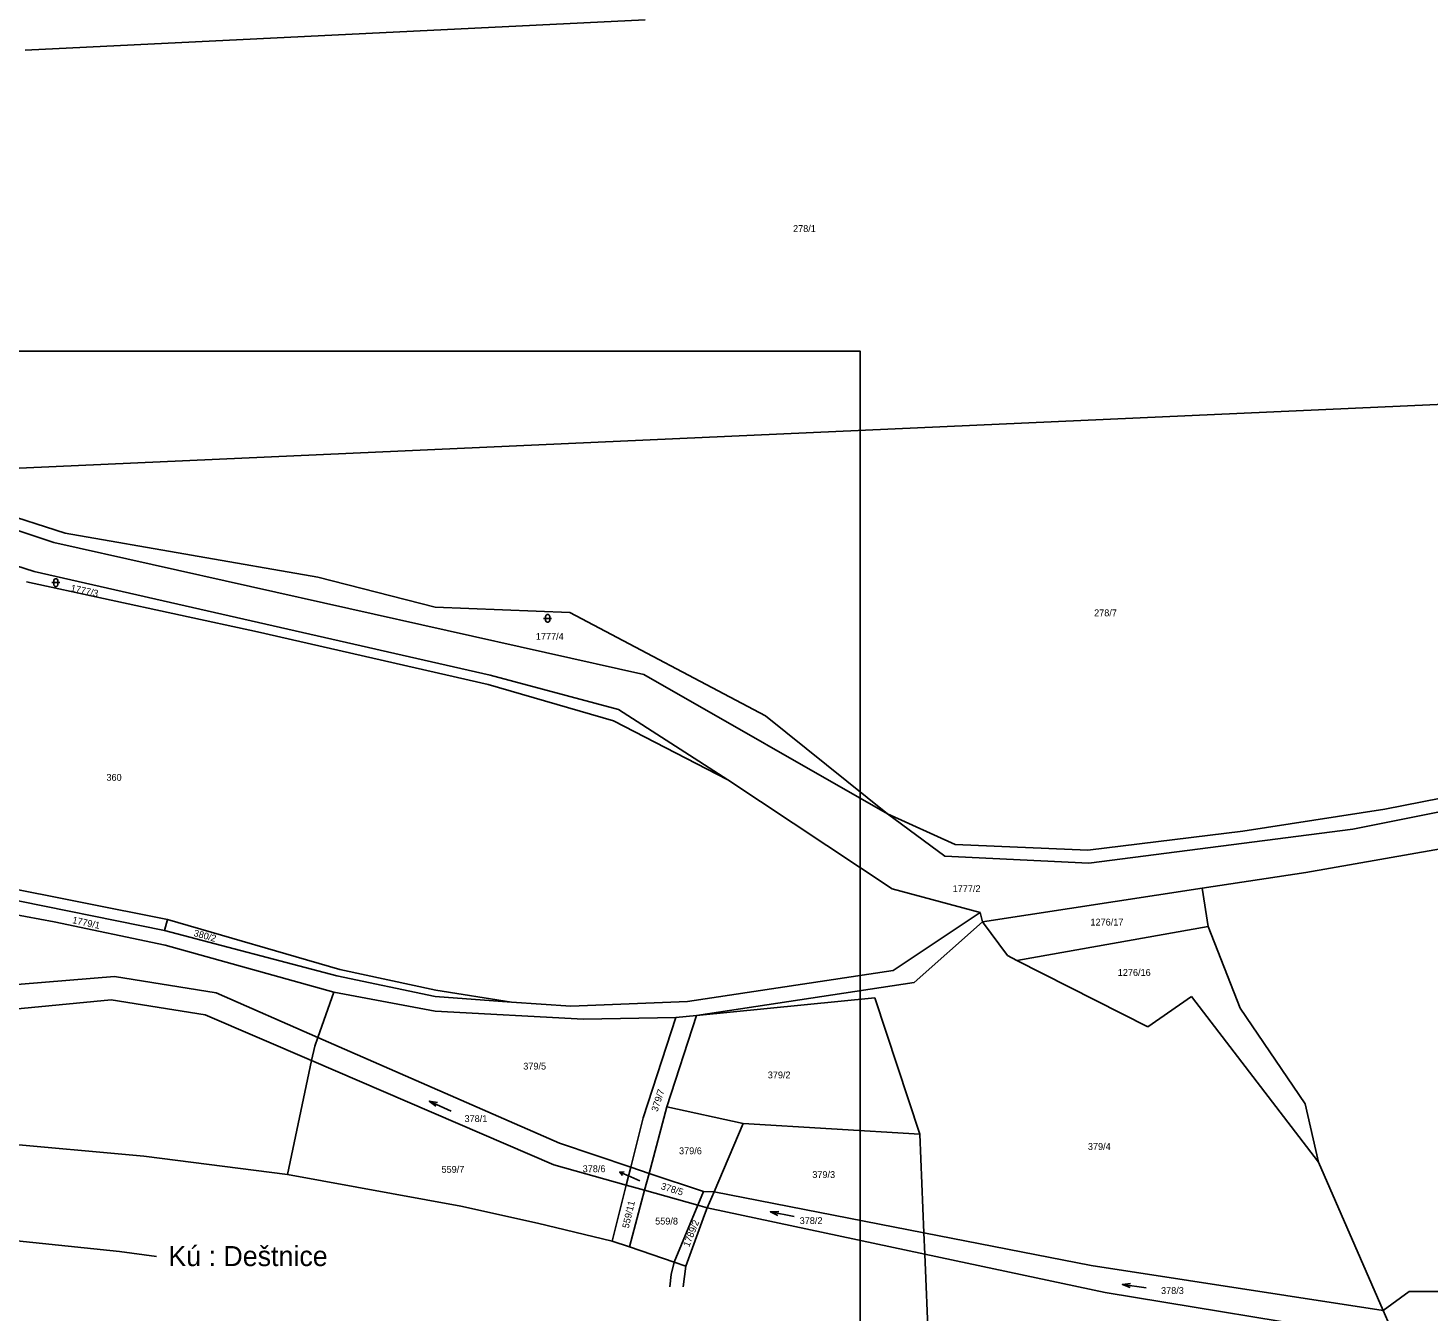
# Model space of a CAD drawing. Extents: x -799786 to -795190, y -1021716 to -1017834.
# Drawn here: x -798627.9 to -798278.5, y -1019029 to -1018708.6 of the extents above; entities that cross this region are included whole.
import ezdxf

# ---------------------------------------------------------------- set-up
doc = ezdxf.new("R2010")
doc.units = 0
for name, color, linetype in [('Default', 7, 'Continuous'), ('KN_HRANICE', 7, 'Continuous'), ('KN_KULTURY', 7, 'Continuous'), ('KN_PARCELY', 7, 'Continuous'), ('KN_SLUCKY', 7, 'Continuous'), ('LEGENDA', 7, 'Continuous')]:
    doc.layers.add(name, color=color, linetype=linetype)

# ---------------------------------------------------------------- blocks, each defined once
blk = doc.blocks.new('316')
at = {"layer": 'Default'}
for points in [[(-1, 1), (0.27, 1), (1, 1)], [(-0.5, 1.5), (-0.4, 1.79), (-0.15, 1.97), (0.16, 1.97), (0.41, 1.79), (0.51, 1.5), (0.51, 0.5), (0.41, 0.21), (0.16, 0.03), (-0.15, 0.03), (-0.4, 0.21), (-0.5, 0.5), (-0.5, 1.5)]]:
    blk.add_lwpolyline(points, dxfattribs=at)
blk = doc.blocks.new('802')
at = {"layer": 'Default'}
blk.add_line((-3, 0), (3, 0), dxfattribs=at)
blk.add_lwpolyline([(1, 0.5), (3, 0), (1, -0.5)], dxfattribs=at)
blk = doc.blocks.new('10292')
at = {"layer": 'Default'}
blk.add_line((0, 3), (0, 0), dxfattribs=at)
blk.add_lwpolyline([(-0.5, 2), (0, 3), (0.5, 2)], dxfattribs=at)

msp = doc.modelspace()

# ---------------------------------------------------------------- linework, layer by layer
at = {"layer": 'KN_HRANICE'}
for p, q in [((-798628.58, -1018714.18), (-798473.83, -1018706.61)), ((-798648.58, -1018819.28), (-798164.43, -1018797.57)), ((-798670.97, -1018817.82), (-798618.58, -1018834.64)), ((-798670.05, -1018820.82), (-798621.41, -1018836.96)), ((-798626.28, -1018844.22), (-798653.49, -1018835.57)), ((-798618.58, -1018834.64), (-798555.54, -1018845.61)), ((-798621.41, -1018836.96), (-798474.17, -1018869.95)), ((-798626.28, -1018844.22), (-798512.51, -1018870.06)), ((-798555.54, -1018845.61), (-798526.25, -1018853.09)), ((-798628.2, -1018846.85), (-798570.58, -1018859.25)), ((-798526.25, -1018853.09), (-798492.65, -1018854.49)), ((-798492.65, -1018854.49), (-798443.82, -1018880.26)), ((-798570.58, -1018859.25), (-798513.02, -1018872.39)), ((-798512.51, -1018870.06), (-798480.48, -1018878.64)), ((-798474.17, -1018869.95), (-798413.42, -1018904.71)), ((-798513.02, -1018872.39), (-798481.79, -1018881.47)), ((-798289.26, -1018903.57), (-798140.92, -1018874.27)), ((-798481.79, -1018881.47), (-798453.21, -1018896.22)), ((-798480.48, -1018878.64), (-798453.21, -1018896.22)), ((-798443.82, -1018880.26), (-798413.42, -1018904.71)), ((-798297.3, -1018908.51), (-798181.63, -1018885.44)), ((-798453.21, -1018896.22), (-798412.19, -1018923.42)), ((-798413.42, -1018904.71), (-798399.11, -1018915.28)), ((-798413.42, -1018904.71), (-798396.51, -1018912.35)), ((-798324.7, -1018909.02), (-798289.26, -1018903.57)), ((-798309.02, -1018919.33), (-798225.73, -1018904.69)), ((-798363.41, -1018913.79), (-798324.7, -1018909.02)), ((-798363.16, -1018917), (-798297.3, -1018908.51)), ((-798396.51, -1018912.35), (-798363.41, -1018913.79)), ((-798399.11, -1018915.28), (-798363.16, -1018917)), ((-798334.83, -1018923.26), (-798309.02, -1018919.33)), ((-798646.5, -1018923.14), (-798593.8, -1018933.78)), ((-798644.85, -1018920.76), (-798593.08, -1018931.09)), ((-798412.19, -1018923.42), (-798390.27, -1018929.32)), ((-798389.65, -1018931.6), (-798334.83, -1018923.26)), ((-798333.38, -1018932.83), (-798334.83, -1018923.26)), ((-798646.74, -1018926.95), (-798621.31, -1018931.61)), ((-798411.98, -1018943.8), (-798390.27, -1018929.32)), ((-798390.27, -1018929.32), (-798389.65, -1018931.6)), ((-798621.31, -1018931.61), (-798593.59, -1018937.5)), ((-798593.08, -1018931.09), (-798593.8, -1018933.78)), ((-798593.8, -1018933.78), (-798550.83, -1018945.14)), ((-798593.08, -1018931.09), (-798550.03, -1018943.53)), ((-798406.71, -1018946.8), (-798389.65, -1018931.6)), ((-798383.44, -1018940.08), (-798389.65, -1018931.6)), ((-798333.38, -1018932.83), (-798381.11, -1018941.26)), ((-798593.59, -1018937.5), (-798551.56, -1018949.18)), ((-798381.11, -1018941.26), (-798383.44, -1018940.08)), ((-798550.03, -1018943.53), (-798526.1, -1018948.66)), ((-798463.3, -1018951.51), (-798411.98, -1018943.8)), ((-798348.39, -1018957.83), (-798381.11, -1018941.26)), ((-798653.61, -1018949.12), (-798606.28, -1018945.31)), ((-798606.28, -1018945.31), (-798580.93, -1018949.34)), ((-798550.83, -1018945.14), (-798526.25, -1018950.31)), ((-798461.06, -1018954.98), (-798406.71, -1018946.8)), ((-798639.41, -1018954.22), (-798607.1, -1018951.14)), ((-798607.1, -1018951.14), (-798583.64, -1018954.81)), ((-798580.93, -1018949.34), (-798555.55, -1018960.46)), ((-798551.56, -1018949.18), (-798555.55, -1018960.46)), ((-798551.56, -1018949.18), (-798526.25, -1018953.93)), ((-798526.25, -1018950.31), (-798507.23, -1018951.65)), ((-798526.1, -1018948.66), (-798507.23, -1018951.65)), ((-798461.06, -1018954.98), (-798416.56, -1018950.62)), ((-798405.32, -1018984.59), (-798416.56, -1018950.62)), ((-798337.55, -1018950.26), (-798348.39, -1018957.83)), ((-798305.84, -1018991.62), (-798337.55, -1018950.26)), ((-798583.64, -1018954.81), (-798557.08, -1018966.24)), ((-798526.25, -1018953.93), (-798489.23, -1018955.9)), ((-798507.23, -1018951.65), (-798492.44, -1018952.69)), ((-798492.44, -1018952.69), (-798463.3, -1018951.51)), ((-798489.23, -1018955.9), (-798466.19, -1018955.48)), ((-798466.19, -1018955.48), (-798474.39, -1018980.52)), ((-798468.45, -1018977.76), (-798461.06, -1018954.98)), ((-798466.19, -1018955.48), (-798461.06, -1018954.98)), ((-798555.55, -1018960.46), (-798556.31, -1018962.63)), ((-798555.55, -1018960.46), (-798495.22, -1018986.9)), ((-798556.31, -1018962.63), (-798557.08, -1018966.24)), ((-798557.08, -1018966.24), (-798563.11, -1018994.64)), ((-798557.08, -1018966.24), (-798496.64, -1018992.23)), ((-798468.45, -1018977.76), (-798472.87, -1018994.39)), ((-798449.39, -1018981.94), (-798468.45, -1018977.76)), ((-798474.39, -1018980.52), (-798477.47, -1018992.85)), ((-798449.39, -1018981.94), (-798456.64, -1018999)), ((-798449.39, -1018981.94), (-798405.32, -1018984.59)), ((-798659.98, -1018984.53), (-798598.93, -1018990.13)), ((-798404.31, -1019009.25), (-798405.32, -1018984.59)), ((-798495.22, -1018986.9), (-798477.47, -1018992.85)), ((-798598.93, -1018990.13), (-798563.11, -1018994.64)), ((-798496.64, -1018992.23), (-798478.58, -1018997.32)), ((-798477.47, -1018992.85), (-798478.58, -1018997.32)), ((-798477.47, -1018992.85), (-798472.87, -1018994.39)), ((-798305.84, -1018991.62), (-798289.67, -1019028.59)), ((-798563.11, -1018994.64), (-798519.87, -1019002.61)), ((-798472.87, -1018994.39), (-798473.99, -1018998.61)), ((-798472.87, -1018994.39), (-798459.27, -1018998.94)), ((-798478.58, -1018997.32), (-798482.07, -1019011.28)), ((-798478.58, -1018997.32), (-798473.99, -1018998.61)), ((-798473.99, -1018998.61), (-798477.75, -1019012.75)), ((-798473.99, -1018998.61), (-798460.7, -1019002.36)), ((-798459.27, -1018998.94), (-798460.7, -1019002.36)), ((-798459.27, -1018998.94), (-798456.64, -1018999)), ((-798456.64, -1018999), (-798404.31, -1019009.25)), ((-798519.87, -1019002.61), (-798500.68, -1019006.85)), ((-798460.7, -1019002.36), (-798466.63, -1019016.52)), ((-798460.7, -1019002.36), (-798458.35, -1019003.02)), ((-798458.35, -1019003.02), (-798459.09, -1019004.76)), ((-798458.35, -1019003.02), (-798404.09, -1019014.54)), ((-798500.68, -1019006.85), (-798482.07, -1019011.28)), ((-798463.72, -1019017.51), (-798459.09, -1019004.76)), ((-798404.31, -1019009.25), (-798362.55, -1019017.42)), ((-798404.09, -1019014.54), (-798404.31, -1019009.25)), ((-798633.02, -1019010.96), (-798604.99, -1019013.85)), ((-798604.99, -1019013.85), (-798595.79, -1019015.16)), ((-798482.07, -1019011.28), (-798477.75, -1019012.75)), ((-798477.75, -1019012.75), (-798466.63, -1019016.52)), ((-798467.39, -1019019.65), (-798466.63, -1019016.52)), ((-798466.63, -1019016.52), (-798463.72, -1019017.51)), ((-798464.36, -1019022.68), (-798463.72, -1019017.51)), ((-798404.09, -1019014.54), (-798359.05, -1019024.1)), ((-798400.12, -1019110.95), (-798404.09, -1019014.54)), ((-798362.55, -1019017.42), (-798289.67, -1019028.59)), ((-798467.39, -1019019.65), (-798467.74, -1019022.68)), ((-798359.05, -1019024.1), (-798293.45, -1019034.91)), ((-798289.67, -1019028.59), (-798283.19, -1019023.84)), ((-798283.19, -1019023.84), (-798256.91, -1019023.98)), ((-798289.67, -1019028.59), (-798288.5, -1019031.25))]:
    msp.add_line(p, q, dxfattribs=at)
msp.add_lwpolyline([(-798305.84, -1018991.62), (-798309.15, -1018977.02), (-798325.36, -1018953.21), (-798333.38, -1018932.83)], dxfattribs=at)
at = {"layer": 'KN_PARCELY'}
msp.add_line((-798475.16, -1018996.24), (-798477.44, -1018995.27), dxfattribs=at)
at = {"layer": 'KN_SLUCKY'}
msp.add_line((-798456.64, -1018999), (-798458.35, -1019003.02), dxfattribs=at)
at = {"layer": 'LEGENDA'}
msp.add_lwpolyline([(-799014.18, -1018789.26), (-798420.18, -1018789.26), (-798420.18, -1019209.26), (-799014.18, -1019209.26)], close=True, dxfattribs=at)

# ---------------------------------------------------------------- block references
at = {"layer": 'KN_KULTURY'}
for p in [(-798620.92, -1018848.01), (-798498.19, -1018856.92)]:
    msp.add_blockref('316', p, dxfattribs=at)
for p, rotation in [((-798525, -1018977.61), 155.214267), ((-798439.65, -1019004.59), 168.335), ((-798351.8, -1019022.52), 172.116522)]:
    msp.add_blockref('802', p, dxfattribs=dict(at, rotation=rotation))
at = {"layer": 'KN_PARCELY', "rotation": 66.97876600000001}
msp.add_blockref('10292', (-798477.44, -1018995.27), dxfattribs=at)

# ---------------------------------------------------------------- texts
at = {"layer": 'KN_PARCELY'}
for s, height, p in [('278/1', 1.7, (-798436.95, -1018759.52)), ('278/7', 1.7, (-798361.83, -1018855.4)), ('1777/4', 1.7, (-798501.13, -1018861.28)), ('360', 1.7, (-798608.28, -1018896.44)), ('1777/2', 1.7, (-798397.12, -1018924.21)), ('1276/17', 1.7, (-798362.74, -1018932.56)), ('1276/16', 1.7, (-798355.93, -1018945.13)), ('379/5', 1.7, (-798504.27, -1018968.5)), ('379/2', 1.7, (-798443.26, -1018970.69)), ('378/1', 1.7, (-798518.93, -1018981.59)), ('379/6', 1.7, (-798465.4, -1018989.62)), ('379/4', 1.7, (-798363.38, -1018988.54)), ('559/7', 1.7, (-798524.67, -1018994.25)), ('378/6', 1.7, (-798489.45, -1018994.1)), ('378/6', 0.1, (-798475.4, -1018996.24)), ('379/3', 1.7, (-798432.15, -1018995.55)), ('559/8', 1.7, (-798471.36, -1019007.16)), ('378/2', 1.7, (-798435.3, -1019007.04)), ('378/3', 1.7, (-798345.13, -1019024.49))]:
    msp.add_text(s, height=height, dxfattribs=at).set_placement(p)
for s, rotation, p in [('1777/3', 347.9, (-798617.32, -1018849.14)), ('1779/1', 347.843, (-798616.9, -1018931.96)), ('380/2', 344.577, (-798586.66, -1018935.16)), ('379/7', 72.021, (-798470.77, -1018979.15)), ('378/5', 342.743, (-798470.07, -1018998.29)), ('559/11', 76.891, (-798477.97, -1019008.23)), ('1789/2', 68.182, (-798462.89, -1019012.91))]:
    msp.add_text(s, height=1.7, rotation=rotation, dxfattribs=at).set_placement(p)
at = {"layer": 'LEGENDA'}
msp.add_text('Kú : Deštnice', height=5, dxfattribs=at).set_placement((-798592.84, -1019017.53))

doc.saveas('drawing.dxf')
